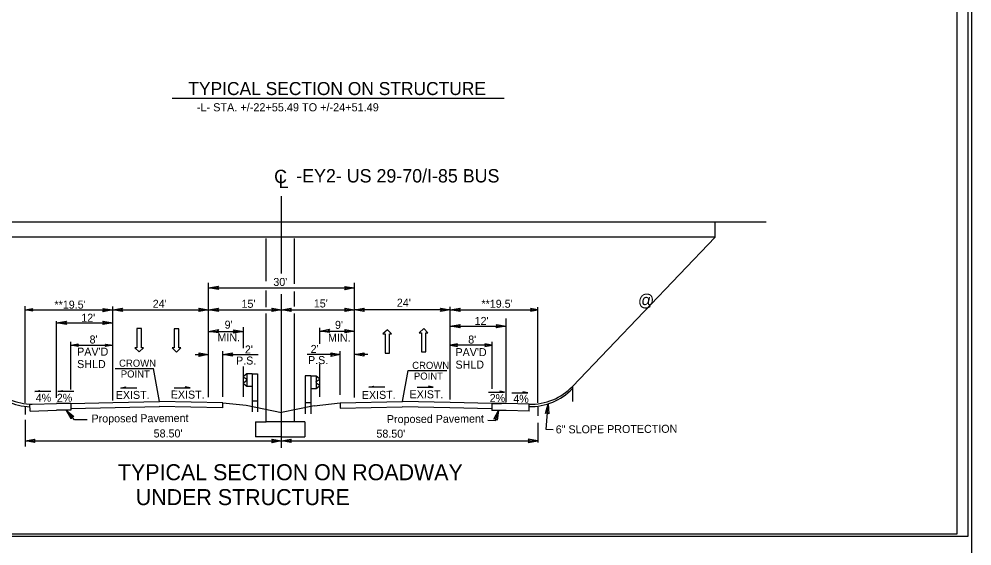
# Model space of a CAD drawing. Extents: x 981824 to 982276, y 44828 to 45204.
# Drawn here: x 981870.7 to 981958.6, y 44916.4 to 44965.1 of the extents above; entities that cross this region are included whole.
import ezdxf

# ---------------------------------------------------------------- set-up
doc = ezdxf.new("R2010")
doc.units = 0
for name, color, linetype in [('Old_Level_1', 7, 'Continuous'), ('Old_Level_11', 7, 'Continuous'), ('Old_Level_18', 7, 'Continuous'), ('Old_Level_3', 7, 'Continuous'), ('Old_Level_4', 7, 'Continuous'), ('Old_Level_50', 7, 'Continuous'), ('Old_Level_51', 7, 'Continuous'), ('Prop Dimension Text', 7, 'Continuous'), ('Prop Terminator CELL', 7, 'Continuous'), ('Typical Guardrail CELL', 7, 'Continuous')]:
    doc.layers.add(name, color=color, linetype=linetype)

msp = doc.modelspace()

# ---------------------------------------------------------------- linework, layer by layer
at = {"layer": 'Old_Level_1'}
for p, q in [((981894.91, 44941.577), (981894.91, 44948.71)), ((981894.91, 44943.517), (981894.91, 44947.192)), ((981939.607, 44946.323), (981850.805, 44946.323)), ((981934.92, 44944.94), (981854.763, 44944.94)), ((981894.91, 44925.501), (981894.91, 44939.696)), ((981894.91, 44928.762), (981894.91, 44939.585)), ((981883.645, 44929.79), (981883.111, 44932.828)), ((981906.059, 44929.786), (981906.594, 44932.63)), ((981871.264, 44929.254), (981871.264, 44928.568)), ((981875.476, 44929.608), (981874.157, 44929.608)), ((981875.476, 44928.965), (981874.157, 44928.965)), ((981893.479, 44927.917), (981893.479, 44929.005)), ((981896.104, 44927.917), (981896.104, 44929.003)), ((981914.307, 44929.602), (981915.205, 44929.602)), ((981915.627, 44929.602), (981914.307, 44929.602)), ((981915.627, 44928.959), (981914.307, 44928.959)), ((981918.547, 44929.241), (981918.547, 44928.453)), ((981871.264, 44928.084), (981871.264, 44925.621)), ((981892.515, 44927.917), (981892.515, 44926.525)), ((981892.515, 44927.917), (981893.479, 44927.917)), ((981896.104, 44927.917), (981893.479, 44927.917)), ((981897.069, 44927.917), (981896.104, 44927.917)), ((981896.104, 44927.917), (981896.104, 44927.917)), ((981897.069, 44927.917), (981897.069, 44926.525)), ((981918.547, 44927.808), (981918.547, 44926.002)), ((981894.85, 44926.525), (981892.515, 44926.525)), ((981894.85, 44926.525), (981897.069, 44926.525)), ((981871.264, 44926.143), (981894.91, 44926.143)), ((981894.91, 44926.143), (981918.547, 44926.143))]:
    msp.add_line(p, q, dxfattribs=at)
at = {"layer": 'Old_Level_11'}
for p, q in [((981934.92, 44944.94), (981934.92, 44946.323)), ((981893.479, 44940.876), (981893.479, 44944.826)), ((981896.104, 44940.647), (981896.104, 44944.826)), ((981921.743, 44931.171), (981934.92, 44944.94)), ((981888.178, 44930.172), (981888.178, 44940.729)), ((981901.642, 44930.155), (981901.642, 44940.722)), ((981888.178, 44940.252), (981894.91, 44940.252)), ((981893.479, 44938.48), (981893.479, 44940.007)), ((981894.91, 44940.252), (981901.642, 44940.252)), ((981896.104, 44938.549), (981896.104, 44939.915)), ((981871.264, 44929.66), (981871.264, 44938.563)), ((981871.264, 44938.223), (981879.336, 44938.223)), ((981879.336, 44929.882), (981879.336, 44938.534)), ((981879.336, 44938.235), (981888.178, 44938.235)), ((981888.178, 44938.235), (981894.91, 44938.235)), ((981893.479, 44929.005), (981893.479, 44937.885)), ((981894.91, 44938.235), (981901.642, 44938.235)), ((981896.104, 44929.003), (981896.104, 44937.885)), ((981910.475, 44938.235), (981901.642, 44938.235)), ((981910.475, 44929.955), (981910.475, 44938.519)), ((981910.475, 44938.235), (981918.547, 44938.235)), ((981918.547, 44929.664), (981918.547, 44938.474)), ((981874.157, 44930.106), (981874.157, 44937.182)), ((981874.157, 44937.041), (981879.336, 44937.041)), ((981915.627, 44929.706), (981915.627, 44937.421)), ((981888.178, 44936.252), (981890.834, 44936.252)), ((981888.178, 44936.252), (981891.388, 44936.252)), ((981891.388, 44934.692), (981891.388, 44936.631)), ((981898.432, 44935.1), (981898.432, 44936.573)), ((981898.432, 44936.278), (981901.642, 44936.278)), ((981910.475, 44936.73), (981915.627, 44936.73)), ((981875.476, 44930.898), (981875.476, 44935.283)), ((981914.329, 44930.949), (981914.329, 44935.283)), ((981875.476, 44934.961), (981879.336, 44934.961)), ((981889.482, 44930.199), (981889.482, 44934.437)), ((981900.332, 44930.404), (981900.332, 44934.412)), ((981914.329, 44934.976), (981910.475, 44934.976)), ((981886.944, 44934.106), (981888.178, 44934.106)), ((981889.482, 44934.106), (981892.753, 44934.106)), ((981900.358, 44934.106), (981897.27, 44934.106)), ((981902.875, 44934.106), (981901.637, 44934.106)), ((981891.388, 44930.199), (981891.388, 44933.009)), ((981898.432, 44930.199), (981898.432, 44933.213)), ((981921.734, 44931.161), (981921.748, 44929.788)), ((981871.714, 44928.894), (981871.699, 44929.537)), ((981875.476, 44929.608), (981879.336, 44929.69)), ((981875.476, 44929.608), (981875.476, 44928.965)), ((981889.468, 44929.666), (981889.468, 44929.191)), ((981889.482, 44929.66), (981891.648, 44929.438)), ((981891.648, 44929.438), (981894.91, 44928.762)), ((981897.908, 44929.371), (981894.91, 44928.762)), ((981897.908, 44929.371), (981900.332, 44929.653)), ((981900.332, 44929.653), (981900.332, 44929.156)), ((981914.289, 44929.091), (981910.438, 44929.185)), ((981914.307, 44929.602), (981910.47, 44929.684)), ((981914.307, 44929.602), (981914.307, 44928.959)), ((981917.759, 44928.88), (981917.759, 44929.522))]:
    msp.add_line(p, q, dxfattribs=at)
for points in [[(981889.08, 44940.105), (981888.178, 44940.252), (981889.08, 44940.416), (981888.965, 44940.252)], [(981900.74, 44940.4), (981901.642, 44940.252), (981900.74, 44940.088), (981900.854, 44940.252)], [(981871.94, 44938.112), (981871.264, 44938.223), (981871.94, 44938.346), (981871.854, 44938.223)], [(981878.433, 44938.371), (981879.336, 44938.223), (981878.433, 44938.059), (981878.548, 44938.223)], [(981880.238, 44938.087), (981879.336, 44938.235), (981880.238, 44938.399), (981880.123, 44938.235)], [(981887.275, 44938.382), (981888.178, 44938.235), (981887.275, 44938.071), (981887.39, 44938.235)], [(981889.08, 44938.087), (981888.178, 44938.235), (981889.08, 44938.399), (981888.965, 44938.235)], [(981894.007, 44938.382), (981894.91, 44938.235), (981894.007, 44938.071), (981894.122, 44938.235)], [(981895.812, 44938.087), (981894.91, 44938.235), (981895.812, 44938.399), (981895.697, 44938.235)], [(981900.74, 44938.382), (981901.642, 44938.235), (981900.74, 44938.071), (981900.854, 44938.235)], [(981902.544, 44938.087), (981901.642, 44938.235), (981902.544, 44938.399), (981902.429, 44938.235)], [(981909.573, 44938.382), (981910.475, 44938.235), (981909.573, 44938.071), (981909.688, 44938.235)], [(981911.378, 44938.087), (981910.475, 44938.235), (981911.378, 44938.399), (981911.263, 44938.235)], [(981917.871, 44938.124), (981918.547, 44938.235), (981917.871, 44938.358), (981917.957, 44938.235)], [(981875.059, 44936.894), (981874.157, 44937.041), (981875.059, 44937.205), (981874.944, 44937.041)], [(981878.433, 44937.189), (981879.336, 44937.041), (981878.433, 44936.877), (981878.548, 44937.041)], [(981889.08, 44936.105), (981888.178, 44936.252), (981889.08, 44936.417), (981888.965, 44936.252)], [(981890.486, 44936.4), (981891.388, 44936.252), (981890.486, 44936.088), (981890.6, 44936.252)], [(981899.334, 44936.13), (981898.432, 44936.278), (981899.334, 44936.442), (981899.219, 44936.278)], [(981900.74, 44936.426), (981901.642, 44936.278), (981900.74, 44936.114), (981900.854, 44936.278)], [(981913.653, 44934.865), (981914.329, 44934.976), (981913.653, 44935.099), (981913.739, 44934.976)], [(981876.153, 44934.85), (981875.476, 44934.961), (981876.153, 44935.084), (981876.067, 44934.961)], [(981878.659, 44935.072), (981879.336, 44934.961), (981878.659, 44934.838), (981878.745, 44934.961)], [(981887.275, 44934.253), (981888.178, 44934.106), (981887.275, 44933.942), (981887.39, 44934.106)], [(981890.385, 44933.958), (981889.482, 44934.106), (981890.385, 44934.27), (981890.27, 44934.106)], [(981899.456, 44934.253), (981900.358, 44934.106), (981899.456, 44933.942), (981899.571, 44934.106)], [(981902.54, 44933.958), (981901.637, 44934.106), (981902.54, 44934.27), (981902.425, 44934.106)], [(981911.152, 44935.087), (981910.475, 44934.976), (981911.152, 44934.853), (981911.066, 44934.976)], [(981872.166, 44925.995), (981871.264, 44926.143), (981872.166, 44926.307), (981872.051, 44926.143)], [(981895.812, 44925.995), (981894.91, 44926.143), (981895.812, 44926.307), (981895.697, 44926.143)], [(981917.645, 44925.995), (981918.547, 44926.143), (981917.645, 44926.307), (981917.76, 44926.143)], [(981894.007, 44926.291), (981894.91, 44926.143), (981894.007, 44925.979), (981894.122, 44926.143)]]:
    msp.add_lwpolyline(points, close=True, dxfattribs=at)
for points in [[(981871.714, 44928.894), (981874.157, 44928.965)], [(981871.92, 44929.532), (981874.157, 44929.608)], [(981875.476, 44929.132), (981883.656, 44929.321)], [(981879.336, 44929.69), (981883.645, 44929.79)], [(981889.468, 44929.191), (981883.635, 44929.321)], [(981889.482, 44929.66), (981883.645, 44929.79)], [(981900.332, 44929.653), (981906.059, 44929.786)], [(981900.332, 44929.156), (981906.027, 44929.287)], [(981910.438, 44929.185), (981906.027, 44929.287)], [(981910.47, 44929.684), (981906.059, 44929.786)], [(981917.759, 44929.522), (981915.627, 44929.602)], [(981917.759, 44928.88), (981915.627, 44928.959)]]:
    msp.add_lwpolyline(points, dxfattribs=at)
for centre, radius, start, end in [((981871.92, 44934.864), 5.58, 223.74207, 267.79074), ((981871.92, 44934.864), 5.331, 223.74207, 270), ((981917.885, 44934.855), 5.334, 268.64166, 316.3192), ((981917.876, 44934.642), 5.334, 268.74198, 316.3192)]:
    msp.add_arc(centre, radius, start, end, dxfattribs=at)
at = {"layer": 'Old_Level_18'}
msp.add_lwpolyline([(981957.237, 45001.552), (981837.237, 45001.552), (981837.237, 44917.552), (981957.237, 44917.552)], close=True, dxfattribs=at)
at = {"layer": 'Old_Level_3'}
for p, q in [((981884.83, 44957.782), (981915.441, 44957.782)), ((981879.554, 44932.828), (981883.111, 44932.828)), ((981906.594, 44932.63), (981910.151, 44932.63))]:
    msp.add_line(p, q, dxfattribs=at)
at = {"layer": 'Old_Level_4'}
for p, q in [((981881.552, 44931.023), (981880.076, 44931.023)), ((981884.991, 44931.039), (981886.467, 44931.039)), ((981904.441, 44931.104), (981902.964, 44931.104)), ((981907.433, 44931.093), (981908.91, 44931.093)), ((981873.626, 44930.686), (981872.15, 44930.686)), ((981875.744, 44930.695), (981874.267, 44930.695)), ((981914.011, 44930.636), (981915.488, 44930.636)), ((981916.157, 44930.581), (981917.633, 44930.581))]:
    msp.add_line(p, q, dxfattribs=at)
for points in [[(981881.573, 44936.504), (981881.573, 44934.741), (981881.388, 44934.741), (981881.778, 44934.351), (981882.188, 44934.741), (981881.983, 44934.741), (981881.983, 44936.504)], [(981885.011, 44936.489), (981885.011, 44934.725), (981884.827, 44934.725), (981885.216, 44934.336), (981885.626, 44934.725), (981885.421, 44934.725), (981885.421, 44936.489)], [(981904.878, 44934.252), (981904.878, 44936.016), (981905.063, 44936.016), (981904.673, 44936.405), (981904.263, 44936.016), (981904.468, 44936.016), (981904.468, 44934.252)], [(981908.234, 44934.352), (981908.234, 44936.115), (981908.418, 44936.115), (981908.028, 44936.505), (981907.618, 44936.115), (981907.823, 44936.115), (981907.823, 44934.352)], [(981872.15, 44930.686), (981872.601, 44930.789), (981872.519, 44930.686)], [(981874.267, 44930.695), (981874.718, 44930.798), (981874.636, 44930.695)], [(981880.076, 44931.023), (981880.527, 44931.126), (981880.445, 44931.023)], [(981886.467, 44931.039), (981886.016, 44931.141), (981886.098, 44931.039)], [(981902.964, 44931.104), (981903.415, 44931.206), (981903.333, 44931.104)], [(981908.91, 44931.093), (981908.459, 44931.196), (981908.541, 44931.093)], [(981915.488, 44930.636), (981915.037, 44930.739), (981915.119, 44930.636)], [(981917.633, 44930.581), (981917.182, 44930.683), (981917.264, 44930.581)]]:
    msp.add_lwpolyline(points, close=True, dxfattribs=at)
at = {"layer": 'Old_Level_50'}
msp.add_lwpolyline([(981958.237, 45001.756), (981824.917, 45001.756), (981824.917, 44917.348), (981958.237, 44917.348)], close=True, dxfattribs=at)
at = {"layer": 'Old_Level_51'}
msp.add_lwpolyline([(981958.597, 45003.552), (981823.877, 45003.552), (981823.877, 44915.552), (981958.597, 44915.552)], close=True, dxfattribs=at)
at = {"layer": 'Prop Terminator CELL'}
for points in [[(981911.375, 44936.575), (981910.475, 44936.73), (981911.38, 44936.89), (981911.265, 44936.73)], [(981914.727, 44936.885), (981915.627, 44936.73), (981914.722, 44936.57), (981914.837, 44936.73)], [(981875.505, 44928.186), (981875.026, 44928.964), (981875.744, 44928.391), (981875.548, 44928.371)], [(981914.504, 44928.143), (981914.913, 44928.959), (981914.804, 44928.047), (981914.684, 44928.203)], [(981919.267, 44928.679), (981919.49, 44929.564), (981919.581, 44928.65), (981919.43, 44928.777)]]:
    msp.add_lwpolyline(points, close=True, dxfattribs=at)
at = {"layer": 'Typical Guardrail CELL'}
for p, q in [((981891.709, 44932.332), (981891.42, 44932.129)), ((981891.709, 44931.799), (981891.42, 44932.002)), ((981891.709, 44931.706), (981891.42, 44931.503)), ((981892.207, 44932.332), (981891.709, 44932.332)), ((981891.709, 44932.332), (981891.709, 44931.173)), ((981891.709, 44931.752), (981891.709, 44931.799)), ((981891.709, 44931.752), (981891.709, 44931.706)), ((981892.207, 44932.332), (981892.207, 44929.847)), ((981892.207, 44932.332), (981892.704, 44932.332)), ((981892.704, 44932.332), (981892.704, 44929.847)), ((981897.599, 44932.141), (981897.101, 44932.141)), ((981897.101, 44932.141), (981897.101, 44929.655)), ((981897.599, 44932.141), (981897.599, 44929.655)), ((981897.599, 44932.141), (981898.096, 44932.141)), ((981898.096, 44932.141), (981898.096, 44930.981)), ((981898.096, 44932.141), (981898.385, 44931.938)), ((981898.096, 44931.608), (981898.385, 44931.811)), ((981898.096, 44931.561), (981898.096, 44931.608)), ((981891.709, 44931.173), (981891.42, 44931.375)), ((981892.207, 44931.173), (981891.709, 44931.173)), ((981897.599, 44930.981), (981898.096, 44930.981)), ((981898.096, 44931.561), (981898.096, 44931.514)), ((981898.096, 44931.514), (981898.385, 44931.311)), ((981898.096, 44930.981), (981898.385, 44931.184)), ((981892.207, 44929.847), (981892.704, 44929.847)), ((981892.207, 44929.847), (981892.207, 44928.838)), ((981892.704, 44929.847), (981892.704, 44928.838)), ((981897.599, 44929.655), (981897.101, 44929.655)), ((981897.101, 44929.655), (981897.101, 44928.647)), ((981897.599, 44929.655), (981897.599, 44928.647))]:
    msp.add_line(p, q, dxfattribs=at)
for points in [[(981876.983, 44928.072), (981875.8, 44928.086), (981875.026, 44928.964)], [(981913.945, 44928.063), (981914.634, 44928.037), (981914.913, 44928.959)], [(981919.974, 44927.172), (981919.311, 44927.197), (981919.49, 44929.564)]]:
    msp.add_lwpolyline(points, dxfattribs=at)
for centre, start, end in [((981891.464, 44932.066), 125.00297, 235.0112), ((981898.341, 44931.874), 304.9888, 54.99702), ((981891.464, 44931.439), 125.0059, 235.0366), ((981898.341, 44931.248), 304.9634, 54.9941)]:
    msp.add_arc(centre, 0.0776, start, end, dxfattribs=at)

# ---------------------------------------------------------------- texts
at = {"layer": 'Old_Level_1'}
for s, height, p in [('C', 1.23, (981894.228, 44949.928)), ('-EY2- US 29-70/I-85 BUS', 1.23031, (981896.264, 44949.988)), ('L', 1.23, (981894.643, 44949.464)), ('TYPICAL SECTION ON ROADWAY ', 1.47637, (981879.816, 44922.515)), ('   UNDER STRUCTURE', 1.47637, (981879.816, 44920.218))]:
    msp.add_text(s, height=height, rotation=360, dxfattribs=at).set_placement(p)
at = {"layer": 'Old_Level_11'}
for s, p in [("30'", (981894.153, 44940.441)), ("24'", (981883.026, 44938.422)), ("15'", (981891.217, 44938.422)), ("15'", (981897.886, 44938.454)), ("24'", (981905.548, 44938.524)), ("58.50'", (981883.111, 44926.461)), ("58.50'", (981903.662, 44926.441))]:
    msp.add_text(s, height=0.7382, dxfattribs=at).set_placement(p)
for s, height, rotation, p in [("**19.5'", 0.7382, 360, (981873.964, 44938.347)), ("**19.5'", 0.7382, 360, (981913.352, 44938.427)), ("12'", 0.7382, 360, (981876.435, 44937.139)), ("9'  ", 0.7382, 360, (981889.659, 44936.499)), ("9' ", 0.7382, 360, (981899.839, 44936.48)), ("12'", 0.7382, 360, (981912.721, 44936.842)), ('MIN.', 0.7382, 360, (981888.996, 44935.33)), ('MIN.', 0.7382, 360, (981899.194, 44935.306)), ("8'", 0.7382, 360, (981877.203, 44935.13)), ("8'", 0.7382, 360, (981912.129, 44935.127)), ("PAV'D ", 0.7382, 360, (981876.055, 44934.01)), ("2'", 0.7382, 360, (981891.528, 44934.209)), ("2'", 0.7382, 360, (981897.592, 44934.259)), ("PAV'D ", 0.7382, 360, (981910.956, 44933.962)), ('SHLD', 0.7382, 360, (981876.055, 44932.861)), ('P.S.', 0.7382, 360, (981890.713, 44933.189)), ('P.S.', 0.7382, 360, (981897.353, 44933.229)), ('SHLD', 0.7382, 360, (981910.956, 44932.814)), ('EXIST.', 0.7382, 0.34377, (981879.616, 44930.006)), ('EXIST.', 0.7382, 359.65623, (981884.685, 44930.057)), ('EXIST.', 0.7382, 0.34377, (981902.314, 44930.009)), ('EXIST.', 0.7382, 359.65623, (981906.719, 44930.086)), ('4%', 0.7382, 0.34377, (981872.237, 44929.746)), ('2%', 0.7382, 0.34377, (981874.18, 44929.746)), ('2%', 0.7382, 359.65623, (981914.107, 44929.726)), ('4%', 0.7382, 359.65623, (981916.286, 44929.671)), ('Proposed Pavement', 0.73819, 0.34377, (981877.383, 44927.836)), ('Proposed Pavement', 0.73819, 0.34377, (981904.634, 44927.78)), ('6" SLOPE PROTECTION', 0.73819, 0.34377, (981920.207, 44926.83))]:
    msp.add_text(s, height=height, rotation=rotation, dxfattribs=at).set_placement(p)
at = {"layer": 'Old_Level_3'}
msp.add_text('TYPICAL SECTION ON STRUCTURE ', height=1.2, dxfattribs=at).set_placement((981886.308, 44958.053))
msp.add_text('@', height=1.107, rotation=360, dxfattribs=at).set_placement((981927.792, 44938.576))
at = {"layer": 'Prop Dimension Text'}
for s, height, p in [('-L- STA. +/-22+55.49 TO +/-24+51.49', 0.75, (981887.098, 44956.55)), ('CROWN', 0.656, (981879.921, 44932.986)), ('CROWN', 0.656, (981906.961, 44932.788)), ('POINT', 0.656, (981880.079, 44931.992)), ('POINT', 0.656, (981907.119, 44931.794))]:
    msp.add_text(s, height=height, dxfattribs=at).set_placement(p)

doc.saveas('drawing.dxf')
